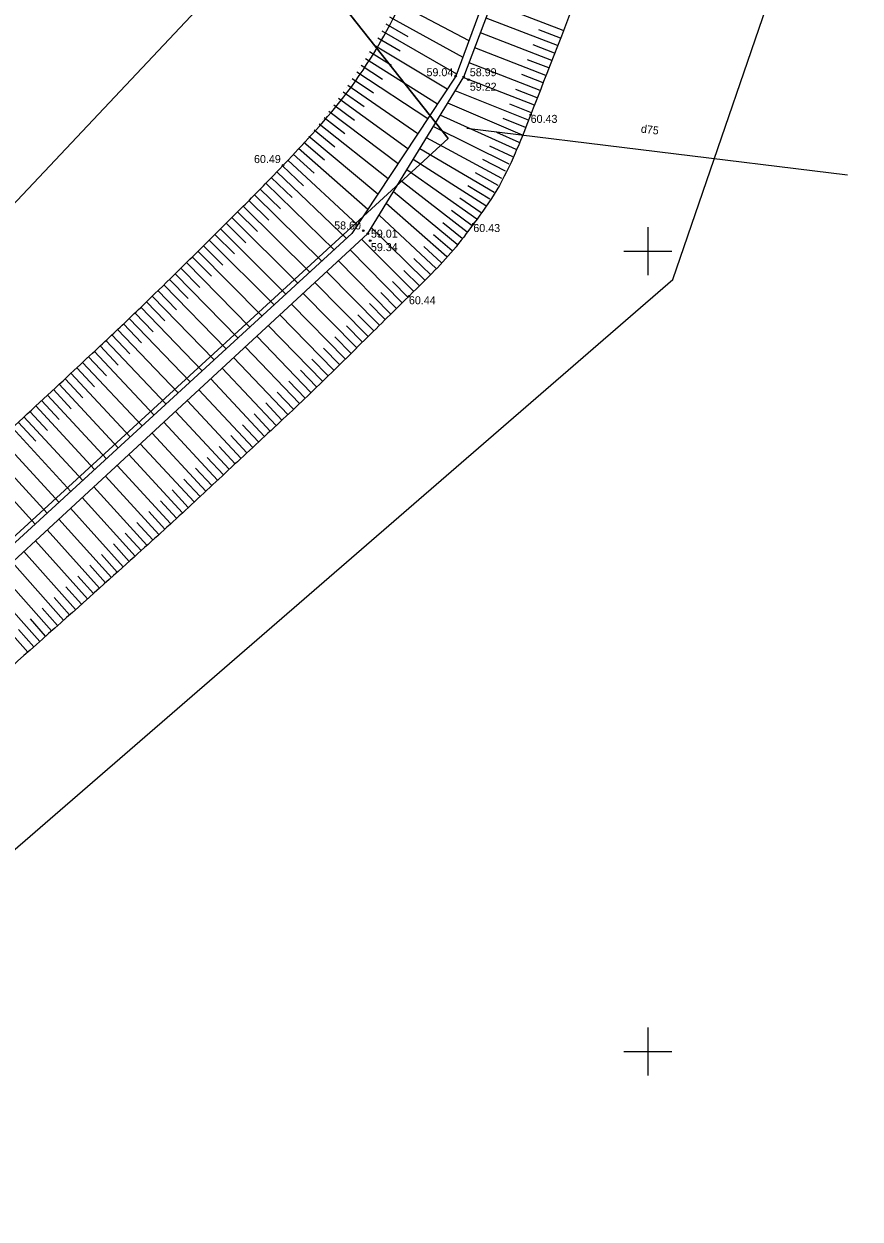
# Model space of a CAD drawing. Extents: x 616607 to 617499, y 408385 to 409695.
# Drawn here: x 617061 to 617113.3, y 408689.5 to 408764.2 of the extents above; entities that cross this region are included whole.
import ezdxf

# ---------------------------------------------------------------- set-up
doc = ezdxf.new("R2010")
doc.units = 0
for name, color, linetype in [('DREN_VADP_####_####_#', 7, 'Continuous'), ('DREN_VADP_####_TKST_#', 7, 'Continuous'), ('GEOD_ELEM_####_####_#', 7, 'Continuous'), ('HIDG_GRAV_####_####_#', 7, 'Continuous'), ('RAMI_UZMR_####_####_#', 7, 'Continuous'), ('RELJ_AATZ_####_TKST_#', 7, 'Continuous'), ('RELJ_ELEM_####_####_#', 7, 'Continuous'), ('RELJ_NOGA_####_####_#', 7, 'Continuous'), ('ROBZ_IERR_####_####_#', 7, 'Continuous')]:
    doc.layers.add(name, color=color, linetype=linetype)

# ---------------------------------------------------------------- blocks, each defined once
blk = doc.blocks.new('PKT')
at = {"layer": 'RELJ_ELEM_####_####_#'}
blk.add_circle((0, 0), 0.05, dxfattribs=at)
blk = doc.blocks.new('KRUSTS')
at = {"layer": 'GEOD_ELEM_####_####_#'}
for p, q in [((0, 1.5), (0, 0)), ((-1.5, 0), (0, 0)), ((0, 0), (0, -1.5)), ((0, 0), (1.5, 0))]:
    blk.add_line(p, q, dxfattribs=at)

msp = doc.modelspace()

# ---------------------------------------------------------------- linework, layer by layer
at = {"layer": 'DREN_VADP_####_####_#'}
msp.add_lwpolyline([(617088.694, 408757.688), (617112.465, 408754.769)], dxfattribs=at)
at = {"layer": 'HIDG_GRAV_####_####_#'}
msp.add_lwpolyline([(616957.708, 408604.801), (616964.717, 408618.582), (616997.814, 408672.816), (617082.506, 408751.106), (617088.497, 408760.889), (617116.937, 408835.934), (617137.451, 408884.548), (617152.78, 408924.733), (617163.79, 408955.542), (617160.997, 408956.152), (617115.742, 408836.043), (617088.001, 408760.943), (617081.506, 408751.106), (616997.147, 408673.705), (616963.717, 408618.582), (616956.708, 408604.801)], dxfattribs=at)
at = {"layer": 'RAMI_UZMR_####_####_#'}
for points in [[(617191.828, 409115.62), (617145.545, 408952.8), (617072.809, 408766.141), (616965.332, 408652.076), (616939.432, 408594.661), (616924.839, 408592.467), (616706.433, 408526.081), (616666.426, 408467.691)], [(616666.426, 408467.691), (616675.529, 408457.882), (616687.228, 408463.356), (616723.888, 408465.775), (616753.554, 408507.232), (616948.282, 408568.831), (616981.528, 408608.531), (617014.563, 408672.892), (617101.571, 408748.246), (617213.472, 409074.039)]]:
    msp.add_lwpolyline(points, dxfattribs=at)
at = {"layer": 'RELJ_NOGA_####_####_#'}
for p, q in [((617084.34, 408765.519), (617088.823, 408763.17)), ((617094.718, 408763.783), (617090.248, 408765.508)), ((617083.548, 408764.058), (617083.548, 408764.057)), ((617083.627, 408764.199), (617085.012, 408763.42)), ((617083.869, 408764.637), (617088.439, 408762.13)), ((617094.358, 408762.85), (617089.893, 408764.573)), ((617083.048, 408763.191), (617083.049, 408763.191)), ((617083.13, 408763.331), (617084.524, 408762.512)), ((617083.3, 408763.623), (617083.3, 408763.623)), ((617083.381, 408763.764), (617088.055, 408761.091)), ((617093.997, 408761.917), (617089.54, 408763.641)), ((617094.538, 408763.316), (617093.198, 408763.834)), ((617082.616, 408762.474), (617083.98, 408761.635)), ((617082.791, 408762.762), (617082.792, 408762.762)), ((617082.875, 408762.901), (617087.47, 408760.14)), ((617093.636, 408760.985), (617089.187, 408762.71)), ((617094.178, 408762.384), (617092.84, 408762.901)), ((617082.265, 408761.912), (617082.265, 408761.912)), ((617082.352, 408762.049), (617086.857, 408759.211)), ((617082.531, 408762.336), (617082.531, 408762.335)), ((617093.275, 408760.052), (617088.833, 408761.774)), ((617093.817, 408761.451), (617092.481, 408761.969)), ((617081.721, 408761.073), (617081.721, 408761.073)), ((617081.811, 408761.208), (617086.249, 408758.29)), ((617081.995, 408761.491), (617081.996, 408761.49)), ((617082.084, 408761.627), (617083.423, 408760.762)), ((617093.456, 408760.518), (617092.122, 408761.036)), ((617081.159, 408760.246), (617081.159, 408760.246)), ((617081.252, 408760.379), (617085.634, 408757.359)), ((617081.443, 408760.658), (617081.443, 408760.657)), ((617081.533, 408760.792), (617082.854, 408759.899)), ((617092.913, 408759.12), (617088.472, 408760.848)), ((617080.579, 408759.431), (617080.579, 408759.431)), ((617080.674, 408759.563), (617085.012, 408756.416)), ((617080.871, 408759.837), (617080.872, 408759.836)), ((617080.965, 408759.969), (617082.271, 408759.042)), ((617092.549, 408758.189), (617087.961, 408760.013)), ((617093.094, 408759.586), (617091.763, 408760.103)), ((617080.079, 408758.759), (617084.398, 408755.485)), ((617080.282, 408759.029), (617080.283, 408759.028)), ((617080.379, 408759.159), (617081.677, 408758.197)), ((617092.169, 408757.264), (617087.496, 408759.255)), ((617092.731, 408758.654), (617091.374, 408759.182)), ((617079.465, 408757.97), (617083.775, 408754.543)), ((617079.674, 408758.235), (617079.675, 408758.234)), ((617079.774, 408758.363), (617081.068, 408757.359)), ((617079.98, 408758.63), (617079.981, 408758.63)), ((617091.767, 408756.348), (617087.035, 408758.501)), ((617092.361, 408757.725), (617090.969, 408758.294)), ((617078.832, 408757.196), (617083.139, 408753.579)), ((617079.048, 408757.455), (617079.049, 408757.455)), ((617079.151, 408757.581), (617080.443, 408756.524)), ((617079.363, 408757.843), (617079.364, 408757.843)), ((617091.34, 408755.444), (617086.599, 408757.789)), ((617091.971, 408756.805), (617090.557, 408757.423)), ((617078.181, 408756.437), (617082.508, 408752.623)), ((617078.403, 408756.691), (617078.404, 408756.691)), ((617078.509, 408756.814), (617079.805, 408755.703)), ((617078.728, 408757.071), (617078.728, 408757.071)), ((617090.883, 408754.554), (617086.167, 408757.084)), ((617091.557, 408755.894), (617090.133, 408756.567)), ((617077.511, 408755.694), (617081.866, 408751.65)), ((617077.739, 408755.943), (617077.74, 408755.943)), ((617077.848, 408756.063), (617079.152, 408754.889)), ((617078.074, 408756.315), (617078.074, 408756.315)), ((617089.872, 408752.829), (617085.336, 408755.726)), ((617090.395, 408753.682), (617085.755, 408756.41)), ((617091.115, 408754.997), (617089.692, 408755.724)), ((617076.824, 408754.968), (617081.178, 408750.805)), ((617077.057, 408755.212), (617077.058, 408755.211)), ((617077.169, 408755.33), (617078.483, 408754.082)), ((617077.401, 408755.576), (617077.401, 408755.575)), ((617089.314, 408752), (617084.95, 408755.096)), ((617076.13, 408754.248), (617080.406, 408750.096)), ((617076.365, 408754.49), (617076.366, 408754.49)), ((617076.478, 408754.607), (617077.771, 408753.359)), ((617076.712, 408754.85), (617076.712, 408754.85)), ((617088.718, 408751.197), (617084.541, 408754.428)), ((617090.643, 408754.116), (617089.239, 408754.906)), ((617075.43, 408753.533), (617079.632, 408749.386)), ((617075.667, 408753.774), (617075.668, 408753.773)), ((617075.781, 408753.89), (617077.052, 408752.645)), ((617076.017, 408754.132), (617076.017, 408754.131)), ((617088.092, 408750.417), (617084.108, 408753.721)), ((617090.138, 408753.253), (617088.759, 408754.095)), ((617074.612, 408752.708), (617074.612, 408752.708)), ((617074.726, 408752.823), (617078.875, 408748.691)), ((617074.965, 408753.063), (617074.965, 408753.062)), ((617075.079, 408753.178), (617076.331, 408751.936)), ((617075.316, 408753.418), (617075.317, 408753.418)), ((617087.441, 408749.659), (617083.661, 408752.99)), ((617089.598, 408752.411), (617088.263, 408753.314)), ((617073.904, 408752.001), (617073.905, 408752.001)), ((617074.019, 408752.116), (617078.127, 408748.004)), ((617074.258, 408752.355), (617074.259, 408752.354)), ((617074.373, 408752.469), (617075.61, 408751.232)), ((617086.767, 408748.919), (617083.207, 408752.251)), ((617089.02, 408751.595), (617087.737, 408752.544)), ((617073.197, 408751.295), (617073.197, 408751.294)), ((617073.312, 408751.409), (617077.389, 408747.328)), ((617073.551, 408751.648), (617073.551, 408751.647)), ((617073.666, 408751.763), (617074.893, 408750.534)), ((617086.076, 408748.196), (617082.727, 408751.466)), ((617088.409, 408750.804), (617087.185, 408751.787)), ((617072.489, 408750.588), (617072.489, 408750.588)), ((617072.604, 408750.703), (617076.646, 408746.646)), ((617072.843, 408750.941), (617072.844, 408750.941)), ((617072.958, 408751.056), (617074.177, 408749.836)), ((617085.373, 408747.486), (617082.121, 408750.749)), ((617087.769, 408750.035), (617086.606, 408751.035)), ((617071.78, 408749.883), (617071.78, 408749.883)), ((617071.895, 408749.997), (617075.896, 408745.958)), ((617072.135, 408750.235), (617072.136, 408750.235)), ((617072.25, 408750.35), (617073.458, 408749.137)), ((617084.661, 408746.783), (617081.404, 408750.086)), ((617087.106, 408749.287), (617086.007, 408750.29)), ((617071.068, 408749.181), (617071.068, 408749.181)), ((617071.184, 408749.295), (617075.141, 408745.265)), ((617071.424, 408749.532), (617071.425, 408749.531)), ((617071.54, 408749.646), (617072.733, 408748.435)), ((617083.949, 408746.081), (617080.667, 408749.405)), ((617086.424, 408748.556), (617085.385, 408749.544)), ((617070.113, 408748.245), (617071.287, 408747.044)), ((617070.354, 408748.481), (617070.354, 408748.481)), ((617070.47, 408748.594), (617074.397, 408744.582)), ((617070.711, 408748.831), (617070.712, 408748.83)), ((617070.827, 408748.944), (617072.011, 408747.739)), ((617083.238, 408745.378), (617079.933, 408748.727)), ((617085.726, 408747.84), (617084.747, 408748.808)), ((617069.397, 408747.547), (617070.561, 408746.35)), ((617069.639, 408747.782), (617069.639, 408747.782)), ((617069.755, 408747.895), (617073.653, 408743.9)), ((617069.997, 408748.131), (617069.997, 408748.13)), ((617082.526, 408744.676), (617079.202, 408748.051)), ((617085.017, 408747.134), (617084.043, 408748.122)), ((617068.562, 408746.738), (617068.563, 408746.737)), ((617068.679, 408746.85), (617069.834, 408745.656)), ((617068.921, 408747.085), (617068.922, 408747.085)), ((617069.038, 408747.198), (617072.904, 408743.213)), ((617069.28, 408747.433), (617069.281, 408747.433)), ((617081.813, 408743.974), (617078.467, 408747.372)), ((617083.594, 408745.729), (617082.606, 408746.73)), ((617084.305, 408746.432), (617083.324, 408747.426)), ((617067.842, 408746.044), (617067.843, 408746.043)), ((617067.959, 408746.156), (617069.106, 408744.964)), ((617068.202, 408746.39), (617068.202, 408746.39)), ((617068.319, 408746.503), (617072.157, 408742.527)), ((617080.385, 408742.574), (617077.016, 408746.03)), ((617081.1, 408743.273), (617077.739, 408746.698)), ((617082.882, 408745.027), (617081.887, 408746.035)), ((617067.12, 408745.352), (617067.12, 408745.351)), ((617067.237, 408745.464), (617068.375, 408744.273)), ((617067.481, 408745.698), (617067.481, 408745.697)), ((617067.598, 408745.81), (617071.405, 408741.838)), ((617079.669, 408741.876), (617076.288, 408745.357)), ((617082.17, 408744.325), (617081.169, 408745.341)), ((617066.395, 408744.663), (617066.396, 408744.662)), ((617066.513, 408744.775), (617067.644, 408743.584)), ((617066.758, 408745.007), (617066.758, 408745.007)), ((617066.875, 408745.119), (617070.657, 408741.151)), ((617078.951, 408741.18), (617075.567, 408744.691)), ((617081.457, 408743.623), (617080.451, 408744.647)), ((617065.422, 408743.745), (617069.15, 408739.768)), ((617065.668, 408743.976), (617065.669, 408743.975)), ((617065.786, 408744.087), (617066.908, 408742.895)), ((617066.032, 408744.319), (617066.032, 408744.319)), ((617066.15, 408744.431), (617069.902, 408740.458)), ((617078.23, 408740.487), (617074.844, 408744.023)), ((617080.743, 408742.923), (617079.733, 408743.955)), ((617064.692, 408743.062), (617068.406, 408739.086)), ((617064.939, 408743.292), (617064.939, 408743.291)), ((617065.057, 408743.403), (617066.172, 408742.209)), ((617065.304, 408743.634), (617065.304, 408743.634)), ((617077.506, 408739.797), (617074.123, 408743.356)), ((617080.027, 408742.225), (617079.014, 408743.264)), ((617063.842, 408742.269), (617063.842, 408742.269)), ((617063.961, 408742.38), (617067.664, 408738.405)), ((617064.208, 408742.61), (617064.208, 408742.609)), ((617064.326, 408742.721), (617065.438, 408741.527)), ((617064.573, 408742.951), (617064.574, 408742.951)), ((617076.78, 408739.11), (617073.411, 408742.698)), ((617079.31, 408741.528), (617078.295, 408742.577)), ((617063.109, 408741.588), (617063.11, 408741.588)), ((617063.228, 408741.699), (617066.92, 408737.722)), ((617063.476, 408741.928), (617063.476, 408741.928)), ((617063.595, 408742.039), (617064.704, 408740.846)), ((617076.05, 408738.427), (617072.691, 408742.032)), ((617078.591, 408740.834), (617077.575, 408741.891)), ((617062.376, 408740.908), (617062.376, 408740.908)), ((617062.495, 408741.019), (617066.178, 408737.042)), ((617062.743, 408741.248), (617062.744, 408741.247)), ((617062.862, 408741.358), (617063.969, 408740.166)), ((617075.318, 408737.745), (617071.956, 408741.353)), ((617077.868, 408740.142), (617076.853, 408741.206)), ((617061.642, 408740.229), (617061.642, 408740.229)), ((617061.761, 408740.339), (617065.437, 408736.362)), ((617062.009, 408740.569), (617062.01, 408740.568)), ((617062.128, 408740.679), (617063.233, 408739.486)), ((617074.586, 408737.063), (617071.222, 408740.674)), ((617077.143, 408739.453), (617076.129, 408740.524)), ((617060.659, 408739.322), (617061.759, 408738.128)), ((617061.026, 408739.661), (617064.693, 408735.679)), ((617061.275, 408739.89), (617061.275, 408739.889)), ((617061.394, 408740), (617062.495, 408738.806)), ((617073.122, 408735.701), (617069.756, 408739.319)), ((617073.855, 408736.382), (617070.488, 408739.996)), ((617076.415, 408738.768), (617075.407, 408739.848)), ((617060.291, 408738.984), (617063.953, 408735)), ((617072.39, 408735.02), (617069.026, 408738.644)), ((617075.684, 408738.086), (617074.676, 408739.168)), ((617059.554, 408738.307), (617063.211, 408734.32)), ((617071.656, 408734.34), (617068.295, 408737.969)), ((617074.22, 408736.723), (617073.211, 408737.806)), ((617074.952, 408737.404), (617073.943, 408738.487)), ((617058.817, 408737.632), (617062.47, 408733.639)), ((617070.922, 408733.661), (617067.57, 408737.298)), ((617073.488, 408736.041), (617072.479, 408737.126)), ((617058.079, 408736.957), (617061.729, 408732.959)), ((617070.186, 408732.984), (617066.84, 408736.624)), ((617072.756, 408735.36), (617071.747, 408736.447)), ((617069.449, 408732.308), (617066.114, 408735.952)), ((617072.023, 408734.68), (617071.015, 408735.768)), ((617068.711, 408731.634), (617065.388, 408735.282)), ((617071.289, 408734.001), (617070.282, 408735.091)), ((617067.971, 408730.961), (617064.665, 408734.613)), ((617070.554, 408733.323), (617069.549, 408734.413)), ((617067.229, 408730.291), (617063.942, 408733.945)), ((617069.818, 408732.646), (617068.816, 408733.738)), ((617065.74, 408728.956), (617062.482, 408732.595)), ((617066.485, 408729.623), (617063.213, 408733.271)), ((617069.08, 408731.971), (617068.081, 408733.064)), ((617064.994, 408728.289), (617061.752, 408731.92)), ((617068.341, 408731.297), (617067.347, 408732.392)), ((617064.248, 408727.624), (617061.021, 408731.245)), ((617066.857, 408729.957), (617065.874, 408731.053)), ((617067.6, 408730.626), (617066.611, 408731.722)), ((617063.501, 408726.958), (617060.29, 408730.569)), ((617066.112, 408729.289), (617065.133, 408730.383)), ((617062.754, 408726.294), (617059.556, 408729.89)), ((617065.367, 408728.622), (617064.392, 408729.713)), ((617062.006, 408725.63), (617058.824, 408729.214)), ((617064.621, 408727.956), (617063.651, 408729.045)), ((617061.258, 408724.966), (617058.092, 408728.537)), ((617063.875, 408727.291), (617062.909, 408728.375)), ((617063.128, 408726.626), (617062.166, 408727.707)), ((617062.38, 408725.962), (617061.424, 408727.039)), ((617061.632, 408725.298), (617060.681, 408726.371))]:
    msp.add_line(p, q, dxfattribs=at)
for points in [[(616952.11, 408607.531), (616956.151, 408614.166), (616960.13, 408620.838), (616964.128, 408627.499), (616969.357, 408636.209), (616974.533, 408644.951), (616979.755, 408653.666), (616982.367, 408658.027), (616985.018, 408662.364), (616987.709, 408666.677), (616989.056, 408668.838), (616990.438, 408670.976), (616991.835, 408673.105), (616992.534, 408674.172), (616993.243, 408675.231), (616993.95, 408676.293), (616994.657, 408677.356), (616995.377, 408678.409), (616996.104, 408679.46), (616998.164, 408682.436), (617000.493, 408685.215), (617003.037, 408687.806), (617005.59, 408690.406), (617008.236, 408692.879), (617011.016, 408695.214), (617013.812, 408697.562), (617016.632, 408699.88), (617019.423, 408702.233), (617020.817, 408703.408), (617022.221, 408704.57), (617023.595, 408705.77), (617024.962, 408706.965), (617026.3, 408708.194), (617027.642, 408709.417), (617031.797, 408713.202), (617035.92, 408717.024), (617040.083, 408720.8), (617044.243, 408724.572), (617048.471, 408728.267), (617052.642, 408732.025), (617056.824, 408735.794), (617060.981, 408739.59), (617065.093, 408743.436), (617067.159, 408745.369), (617069.191, 408747.335), (617071.208, 408749.318), (617072.22, 408750.314), (617073.221, 408751.32), (617074.226, 408752.322), (617075.234, 408753.328), (617076.23, 408754.338), (617077.212, 408755.375), (617081.698, 408760.112), (617084.989, 408765.985), (617087.243, 408772.093), (617089.541, 408778.321), (617091.528, 408784.634), (617093.829, 408790.846), (617099.646, 408806.547), (617105.384, 408822.279), (617111.331, 408837.932), (617116.967, 408852.766), (617122.795, 408867.526), (617128.465, 408882.346), (617134.52, 408898.17), (617140.109, 408914.165), (617146.15, 408930), (617147.203, 408932.762), (617148.413, 408935.46), (617149.608, 408938.162), (617150.805, 408940.87), (617152.218, 408943.437), (617153.491, 408946.151), (617155.134, 408949.654), (617156.252, 408953.338), (617157.386, 408956.937), (617157.388, 408956.942), (617157.376, 408956.956), (617157.382, 408956.955), (617158.587, 408956.687), (617159.792, 408956.42), (617160.997, 408956.152)], [(617163.79, 408955.542), (617165.45, 408955.194), (617167.11, 408954.846), (617168.77, 408954.498), (617168.913, 408954.468), (617169.034, 408954.324), (617169.074, 408954.183), (617169.128, 408953.99), (617169.08, 408953.773), (617169.007, 408953.587), (617168.835, 408953.148), (617168.665, 408952.708), (617168.483, 408952.272), (617167.485, 408949.894), (617166.495, 408947.512), (617165.486, 408945.138), (617164.477, 408942.762), (617163.444, 408940.395), (617162.435, 408938.019), (617160.416, 408933.265), (617158.392, 408928.513), (617156.542, 408923.692), (617150.713, 408908.507), (617144.931, 408893.305), (617139.111, 408878.118), (617136.201, 408870.523), (617133.294, 408862.928), (617130.378, 408855.336), (617127.463, 408847.744), (617124.504, 408840.168), (617121.547, 408832.592), (617116.624, 408819.98), (617111.621, 408807.399), (617106.663, 408794.801), (617101.918, 408782.741), (617097.386, 408770.604), (617092.68, 408758.522), (617091.748, 408756.128), (617090.638, 408753.8), (617089.099, 408751.701), (617087.891, 408750.055), (617086.512, 408748.607), (617085.075, 408747.191), (617082.094, 408744.254), (617079.138, 408741.303), (617076.078, 408738.453), (617073.02, 408735.605), (617069.97, 408732.751), (617066.861, 408729.96), (617060.644, 408724.38), (617054.349, 408718.89), (617048.124, 408713.32), (617041.902, 408707.753), (617035.717, 408702.149), (617029.576, 408696.491), (617026.506, 408693.662), (617023.563, 408690.704), (617020.596, 408687.763), (617017.626, 408684.818), (617014.683, 408681.855), (617011.931, 408678.697), (617008.517, 408674.776), (617005.359, 408670.661), (617002.288, 408666.476), (616999.318, 408662.428), (616996.36, 408658.374), (616993.424, 408654.302), (616990.492, 408650.235), (616987.575, 408646.161), (616984.691, 408642.059), (616983.288, 408640.063), (616981.951, 408638.02), (616980.703, 408635.922), (616979.453, 408633.819), (616978.237, 408631.7), (616977.033, 408629.572), (616975.83, 408627.444), (616974.65, 408625.305), (616973.452, 408623.174), (616972.259, 408621.052), (616970.984, 408618.974), (616969.729, 408616.893), (616969.613, 408616.701), (616969.41, 408616.592), (616969.29, 408616.383), (616968.995, 408615.872), (616968.948, 408615.291), (616969.02, 408614.761), (616969.09, 408614.251), (616969.19, 408613.683), (616969.493, 408613.251)]]:
    msp.add_open_spline(points, degree=3, dxfattribs=at)
at = {"layer": 'ROBZ_IERR_####_####_#'}
for points in [[(617055.284, 408797.783), (617087.528, 408757.04), (616999.181, 408676.019), (616968.565, 408608.405), (616958.517, 408604.593), (616940.576, 408582.801), (616889.795, 408568.012), (616805.459, 408543.657), (616730.494, 408522.344), (616717.135, 408556.579)], [(617001.984, 408630.998), (616968.565, 408608.405), (616999.181, 408676.019), (617087.528, 408757.04), (617055.515, 408797.492)]]:
    msp.add_lwpolyline(points, dxfattribs=at)

# ---------------------------------------------------------------- block references
at = {"layer": 'GEOD_ELEM_####_####_#'}
for p in [(617100, 408750), (617100, 408700)]:
    msp.add_blockref('KRUSTS', p, dxfattribs=at)
at = {"layer": 'RELJ_ELEM_####_####_#'}
for p in [(617088.001, 408760.943), (617088.497, 408760.889), (617088.794, 408760.721), (617092.68, 408758.522), (617077.212, 408755.375), (617082.226, 408751.285), (617089.099, 408751.701), (617082.506, 408751.106), (617082.656, 408750.669), (617085.075, 408747.191)]:
    msp.add_blockref('PKT', p, dxfattribs=at)

# ---------------------------------------------------------------- texts
at = {"layer": 'DREN_VADP_####_TKST_#'}
msp.add_text('d75', height=0.5, rotation=352.99799, dxfattribs=at).set_placement((617099.547, 408757.421))
at = {"layer": 'RELJ_AATZ_####_TKST_#'}
for s, p in [('59.04', (617086.173, 408760.936)), ('58.99', (617088.878, 408760.936)), ('59.22', (617088.878, 408760.03)), ('60.43', (617092.68, 408758.022)), ('60.49', (617075.397, 408755.511)), ('58.60', (617080.404, 408751.363)), ('59.01', (617082.7, 408750.851)), ('60.43', (617089.099, 408751.201)), ('59.34', (617082.7, 408750.01)), ('60.44', (617085.075, 408746.691))]:
    msp.add_text(s, height=0.5, dxfattribs=at).set_placement(p)

doc.saveas('drawing.dxf')
